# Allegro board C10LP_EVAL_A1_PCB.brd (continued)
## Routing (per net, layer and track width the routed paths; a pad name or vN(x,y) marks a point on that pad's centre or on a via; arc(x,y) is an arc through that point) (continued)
RG_RXD1: length 2
  TOP w0.142: R105.2 26.64,46.35 26.61,46.39 U14.4
RG_RXD2: length 2.1
  TOP w0.142: U14.3 26.11,46.01 25.63,45.53 R106.2
RG_RXD3: length 2.2
  TOP w0.142: U14.1 25.11,46.49 24.99,46.38 24.99,45.63 R107.2
RUP2: length 5.4
  TOP w0.135: U1.M10 41.48,27.32 v2(41.48,27.3)
  BOTTOM w0.135: R12.2 46.2,27.68 41.85,27.68 v2(41.48,27.3)
SYS_CONF_DONE: length 39.5
  TOP w0.135: U3.K1 52.51,67.47 54.18,65.81 56.08,65.81 57.18,64.72 57.18,64.16 58.98,62.36 62.64,62.36 63.88,61.11 66.22,61.11 67.77,59.56 69.85,59.56 71.93,57.48 71.93,50.14 72.95,49.12 77.42,49.12 78.11,48.44 D5.2
SYS_CONF_DONE_R: length 1.2
  TOP w0.135: D5.1 R135.2
SYS_I2C_SCL: length 98.6
  TOP w0.135: U3.G13 41.12,65.07 41.05,65.15 40.2,65.15 R55.2 40.22,64.69 40.67,64.69 41.05,64.31 v1(41.05,63.37)
  ART03 w0.102: v1(72.47,67.03) 71.98,66.55 71.98,61.24 78.87,54.36 78.87,52.32 77.06,50.52 77.06,37.26 77.7,36.63 77.7,34.39 77.52,34.21 77.52,26.23 v1(78.05,25.69)
  BOTTOM w0.135: v1(78.05,25.69) R263.1 ; v1(41.05,63.37) 41.07,63.35 41.99,63.35 42.44,62.89 42.9,62.89 43.38,63.37 44.63,63.37 44.94,63.68 44.94,64.04 45.75,64.85 45.75,66.45 45.97,66.67 46.33,66.67 47.29,67.64 47.29,70.79 49.28,72.77 53.82,72.77 58.09,77.04 66.99,77.04 68.15,75.88 68.15,74.75 71.02,71.88 71.02,68.48 v1(72.47,67.03)
SYS_I2C_SDA: length 82.7
  TOP w0.135: U3.H8 v2(46.15,66.28)
  ART03 w0.102: v1(78.31,35.56) 78.31,36.73 77.5,37.54 77.5,50.29 79.32,52.12 79.32,54.51 72.49,61.34 v1(72.49,66.19)
  BOTTOM w0.135: R264.1 78.82,28.59 R56.2 79.21,29.5 79.4,29.69 79.4,30.96 78.66,31.7 78.66,34.7 78.31,35.05 v1(78.31,35.56) ; v1(72.49,66.19) 69.88,68.81 69.88,72.31 67.55,74.64 67.55,75.83 66.8,76.58 58.29,76.58 53.98,72.26 49.59,72.26 48.15,70.82 48.15,67.61 48.01,67.48 47.49,67.48 46.29,66.28 v2(46.15,66.28)
TPIAN: length 35.8
  TOP w0.107: U14.27 29.61,54.35 29.69,54.43 29.69,57.48 32.13,59.92 32.74,60.53 33.5,60.53 38.35,65.38 38.35,76.67 35.48,79.54 35.48,80.75 35.28,80.95 35.28,81.2 35.48,81.41 35.48,81.65 35.28,81.85 35.12,81.85 34.89,81.62 34.68,81.62 34.46,81.85 34.28,81.85 33.73,81.31 U28.11
TPIAP: length 36
  TOP w0.107: U28.12 33.73,82.58 34.12,82.18 35.42,82.18 35.81,81.79 35.81,79.68 38.68,76.81 38.68,65.24 33.64,60.2 32.88,60.2 30.02,57.34 30.02,54.38 30.11,54.3 U14.26
TPIBN: length 31.9
  TOP w0.107: U28.8 33.73,77.5 34.27,78.03 34.66,78.03 34.85,77.84 34.85,77.5 35.08,77.27 35.42,77.27 35.59,77.1 35.59,76.76 35.79,76.56 36.13,76.56 37.24,75.45 37.24,65.85 33.39,62 31.36,62 28.69,59.33 28.69,54.4 28.61,54.31 U14.29
TPIBP: length 32
  TOP w0.107: U28.9 33.73,78.77 34.13,78.36 34.79,78.36 35.08,78.07 37.57,75.59 37.57,65.71 33.53,61.67 31.5,61.67 29.02,59.2 29.02,54.47 29.11,54.38 U14.28
TPICN: length 29.2
  TOP w0.107: U28.5 33.73,73.69 34.2,74.16 34.48,74.16 34.75,73.89 34.98,73.89 35.24,74.16 35.57,74.16 36.12,73.61 36.12,73.25 35.86,73 35.86,72.8 36.12,72.54 36.12,66.48 33.06,63.42 30.09,63.42 27.19,60.53 27.19,56.31 R108.2 27.19,55.37 27.19,54.5 27.11,54.41 U14.32
TPICP: length 29.3
  TOP w0.107: U14.31 27.61,54.41 27.52,54.5 27.52,55.37 R110.2 27.52,56.31 27.52,60.39 30.23,63.09 33.2,63.09 36.45,66.34 36.45,73.75 35.71,74.49 34.2,74.49 33.73,74.96 U28.6
TPIDN: length 24.9
  TOP w0.107: U14.34 26.11,54.43 26.19,54.51 26.19,55 25.55,55.64 25.55,61.35 30.34,66.14 33.88,66.14 35.03,67.28 35.03,67.51 34.78,67.76 34.78,68.11 35.03,68.35 35.03,68.99 34.72,69.29 34.72,69.6 35,69.87 35,70.12 34.75,70.37 34.23,70.37 33.73,69.88 U28.2
TPIDP: length 25
  TOP w0.107: U14.33 26.61,54.42 26.52,54.51 26.52,55.14 25.88,55.78 25.88,61.21 30.48,65.81 34.02,65.81 35.36,67.15 35.36,70.23 34.89,70.7 34.18,70.7 33.73,71.15 U28.3
USB_5V: length 8.8
  BOTTOM w0.508: 71.32,63.35 71.22,63.35 70.71,63.86 65.84,63.86 64.95,64.74 64.95,65.41 64.36,65.99 R31.1
USB_ADDR0: length 26.3
  TOP w0.135: U1.A10 41.84,37.7 41.84,38.14 41.58,38.4 41.58,40.39 44.42,43.23 44.42,54.04 45.35,54.97 45.35,56.56 46.23,57.44 46.23,59.16 U3.A7
USB_ADDR1: length 25.9
  TOP w0.135: U1.A11 v2(42.64,37.32) ; v1(43.41,44.35) 42.8,44.96 42.8,49.33 43.13,49.66 43.13,56.26 43.94,57.07 43.94,58.75 44.95,59.75 U3.A10
  ART03 w0.102: v2(42.64,37.32) 42.24,37.72 42.24,43.64 42.95,44.35 v1(43.41,44.35)
USB_CLK: length 71.6
  TOP w0.135: v1(67.67,72.69) 67.49,72.69 67.49,72.69 U6.13
  ART03 w0.102: v1(67.67,72.69) 68.63,71.73 68.63,67.03 69.42,66.24 69.42,63.3 68.2,62.08 67.16,62.08 66.55,61.47 66.55,59.05 66.4,58.9 66.4,49.35 67.74,48.01 67.74,34.44 66.78,33.48 64.06,33.48 63.63,33.91 62.87,33.91 62.53,33.58 53.75,33.58 48.44,38.89 v1(46.86,38.89)
  BOTTOM w0.135: R248.1 42.63,38.89 v1(46.86,38.89) ; v1(67.67,72.69) 67.42,72.94 R247.2
USB_DATA0: length 25.8
  TOP w0.135: U1.A15 45.84,37.56 46.23,37.95 46.23,39.14 48.46,41.38 48.46,55.17 50.06,56.77 50.06,58.27 50.55,58.76 50.55,60.27 U3.A3
USB_DATA1: length 28.3
  TOP w0.135: U1.B14 45.44,36.08 45.44,37.79 45.77,38.13 45.77,39.45 47.32,41 47.32,44.17 48.07,44.93 48.07,48.62 47.32,49.38 47.32,52.4 48.07,53.15 48.07,55.33 49.67,56.93 49.67,58.46 50.16,58.95 50.16,60.69 U3.B3
USB_DATA2: length 26.4
  TOP w0.135: U1.A14 45.04,38.05 45.31,38.33 45.31,39.75 46.91,41.35 46.91,44.35 47.69,45.12 47.69,48.38 46.91,49.15 46.91,52.72 47.69,53.49 47.69,55.51 49.29,57.11 49.29,58.62 49.75,59.08 U3.A4
USB_DATA3: length 28.3
  TOP w0.135: U1.B13 44.64,36.08 44.64,39.97 46.51,41.83 46.51,44.55 47.3,45.34 47.3,48.11 46.51,48.89 46.51,52.98 47.3,53.77 47.3,55.68 48.34,56.72 48.34,58.48 49.38,59.52 49.38,60.71 U3.B4
USB_DATA4: length 26.6
  TOP w0.135: U3.A5 48.95,59.64 47.82,58.51 47.82,56.78 46.91,55.87 46.91,54.08 46.1,53.27 46.1,48.51 46.91,47.71 46.91,45.51 46.1,44.7 46.1,42.09 44.04,40.03 44.04,38.28 44.24,38.08 U1.A13
USB_DATA5: length 28.6
  TOP w0.135: U1.B12 43.84,36.08 43.84,37.9 43.51,38.23 43.51,40.18 45.69,42.37 45.69,44.86 46.52,45.68 46.52,47.38 45.69,48.21 45.69,53.58 46.52,54.41 46.52,56.05 47.43,56.95 47.43,58.67 48.54,59.78 48.54,60.67 U3.B5
USB_DATA6: length 26.2
  TOP w0.135: U3.A6 48.15,60.03 47.51,59.39 47.51,59.3 47.04,58.84 47.04,57.15 46.13,56.24 46.13,54.61 45.3,53.78 45.3,42.79 42.9,40.39 42.9,38.15 43.48,37.57 43.48,36.52 U1.A12
USB_DATA7: length 28
  TOP w0.135: U3.B6 47.75,60.67 47.75,60.09 46.62,58.96 46.62,57.28 45.74,56.4 45.74,54.79 44.86,53.9 44.86,43.03 42.24,40.41 42.24,36.08 U1.B10
USB_DISABLEN: length 21.7
  TOP w0.135: v1(39.52,69.9) 39.52,68.96 41.81,66.67 U3.J13 ; J2.2 v1(50.44,75.44)
  BOTTOM w0.135: v1(50.44,75.44) 50.43,75.43 R59.1 47.98,74.3 47.88,74.19 42.62,74.19 41.38,72.95 41.33,72.95 40.16,71.78 40.16,70.48 39.57,69.9 v1(39.52,69.9)
USB_EMPTY: length 35.3
  TOP w0.135: U3.E6 47.73,63.06 v2(47.73,62.23) ; v2(45.44,34.48) U1.D14
  ART03 w0.102: v2(47.73,62.23) 48.13,61.82 48.13,59.21 48.31,59.03 48.31,45.14 45.85,42.67 45.85,34.89 v2(45.44,34.48)
  BOTTOM w0.135: v2(47.73,62.23) 48.16,61.8 48.16,61.32 47.83,60.99 47.83,59.11 48.23,58.7 R52.1
USB_FULL: length 32.5
  TOP w0.135: v2(43.84,34.48) U1.D12 ; U3.C9 v2(45.35,61.47)
  ART03 w0.102: v2(45.35,61.47) 45.8,61.02 45.8,60.35 46.96,59.18 46.96,45.14 44.25,42.42 44.25,34.89 v2(43.84,34.48)
  BOTTOM w0.135: v2(45.35,61.47) 44.4,60.53 44.4,60.21 R51.1
USB_OEN: length 31
  TOP w0.135: U3.A9 45.31,59.84 45.31,57.67 44.58,56.94 44.58,55.47 43.54,54.43 43.54,45.24 v1(43.43,45.14) ; v2(41.44,32.88) U1.F9
  ART03 w0.102: v1(43.43,45.14) 42.75,45.14 41.83,44.22 41.83,36.83 41.05,36.04 41.05,34.29 41.25,34.09 41.58,34.09 41.83,33.83 41.83,33.27 v2(41.44,32.88)
USB_RDN: length 28.9
  TOP w0.135: U1.D11 v2(43.04,34.48) ; v1(43.41,43.54) 42.27,44.68 42.27,49.53 42.67,49.94 42.67,56.59 43.48,57.4 43.48,58.95 44.56,60.03 44.56,60.69 U3.B10
  ART03 w0.102: v1(43.41,43.54) 43.46,43.48 43.46,34.9 v2(43.04,34.48)
USB_RESETN: length 28
  TOP w0.135: U1.C9 40.64,35.28 40.64,40.08 43.97,43.41 43.97,54.15 44.97,55.15 44.97,56.78 45.8,57.61 45.8,59.53 U3.A8
USB_SCL: length 31.3
  TOP w0.135: v2(45.44,35.28) U1.C14 ; U3.E8 v2(46.15,63.07)
  ART03 w0.102: v2(46.15,63.07) 46.53,62.69 46.53,60.3 47.35,59.49 47.35,44.86 45.44,42.95 v2(45.44,35.28)
  BOTTOM w0.135: R54.1 45.4,62.33 v2(46.15,63.07)
USB_SDA: length 34
  TOP w0.135: U1.E9 v2(41.44,33.68) ; U3.C10 v2(44.55,61.47)
  ART03 w0.102: v2(44.55,61.47) 44.88,61.14 44.88,60.58 46.61,58.85 46.61,49.71 41.38,44.48 41.38,38.51 40.64,37.77 40.64,36.7 40.79,36.55 40.79,33.88 41,33.68 v2(41.44,33.68)
  BOTTOM w0.135: v2(44.55,61.47) 44.15,61.07 44.15,60.92 R53.1
USB_WRN: length 28
  TOP w0.135: U3.A11 43,59.13 43,58.09 42.72,57.81 41.88,57.81 40.26,56.18 40.26,51.66 41.81,50.11 41.81,44.04 v1(42.7,43.15) ; v2(43.05,36.91) 43.05,36.09 U1.B11
  ART03 w0.102: v1(42.7,43.15) 43.05,42.8 v2(43.05,36.91)
USER_DIP0: length 69.1
  TOP w0.135: v1(66.94,53.84) R147.1 68.21,53.84 68.4,54.03 SW1.6
  TOP w0.137: v2(47.5,27.68) U1.M16
  ART03 w0.102: v1(70.38,50.65) 73.89,50.65 75.06,49.48 75.06,30.71 74.12,29.77 74.12,28.3 74.35,28.07 74.35,26.9 73,25.55 68.12,25.55 67.34,24.77 66.8,24.77 64.95,22.91 63.88,22.91 57.73,29.06 47.37,29.06 47.02,28.7 47.02,28.09 47.43,27.68 v2(47.5,27.68)
  BOTTOM w0.135: v1(66.94,53.84) 70.13,50.65 v1(70.38,50.65)
USER_DIP1: length 59.7
  TOP w0.135: U1.A8 v2(40.24,37.04) ; SW1.7 68.2,52.76 68.11,52.67 R146.1 v1(66.94,52.67) ; v1(69.01,31.42) 68.12,30.53 63.75,30.53 63.32,30.96 61.57,30.96 59.94,32.59 53.39,32.59 50.95,35.03 v1(49.86,35.03)
  ART03 w0.102: v1(69.01,31.42) 69.88,32.28 69.88,47.6 68.55,48.92 68.55,51.05 v1(66.94,52.67) ; v1(46.86,37.8) 46.58,37.52 46.58,36.7 47.6,35.69 48.59,35.69 49.25,35.03 v1(49.86,35.03)
  BOTTOM w0.135: v1(46.86,37.8) 44.55,37.8 43.18,36.42 40.86,36.42 v2(40.24,37.04)
USER_DIP2: length 51
  TOP w0.135: v1(66.92,50.46) R145.1 67.64,50.93 68.2,51.49 SW1.8 ; U1.A9 v2(41.04,37.04)
  ART03 w0.102: v1(49.53,37.13) 53.49,33.17 62.71,33.17 63.02,33.48 63.47,33.48 63.91,33.05 67.06,33.05 68.15,34.14 68.15,49.23 v1(66.92,50.46)
  BOTTOM w0.135: v2(41.04,37.04) 41.74,37.04 43.08,38.38 48.29,38.38 v1(49.53,37.13)
USER_LED0: length 57.4
  TOP w0.135: U1.L14 v2(45.44,28.08) ; D6.2 78.32,43.23 78.16,43.07 78.16,41.48 77.7,41.02 74.78,41.02 74.24,41.55 v1(72.62,41.55)
  ART03 w0.102: v2(45.44,28.08) 45.78,28.08 47.19,29.49 57.94,29.49 64.03,23.39 64.85,23.39 66.62,25.17 67.08,25.17 67.87,25.96 72.34,25.96 73.33,26.95 73.33,29.79 74.42,30.89 74.42,39.75 v1(72.62,41.55)
USER_LED0_R: length 1.2
  TOP w0.135: D6.1 R138.2
USER_LED1: length 52
  TOP w0.135: 47.19,28.88 47.25,28.93 47.93,28.93 v1(48.31,28.55) ; v1(75.59,35.74) 76.23,36.37 77.65,36.37 78.11,36.83 78.11,37.74 78.38,38.02 D7.2
  TOP w0.137: U1.K15 46.24,28.88 47.19,28.88
  ART03 w0.102: v1(75.59,35.74) 75.59,27.53 73.13,25.07 68.28,25.07 67.54,24.33 66.95,24.33 65.53,22.91 65.53,21.26 64.92,20.65 63.4,20.65 62.97,21.08 62.97,23.19 57.58,28.58 51.49,28.58 51,28.09 49.12,28.09 48.77,28.45 48.41,28.45 v1(48.31,28.55)
USER_LED1_R: length 1.2
  TOP w0.135: D7.1 R140.2
USER_LED2: length 42.2
  TOP w0.135: v2(45.44,29.68) U1.J14 ; D8.2 78.24,32.82 77.3,31.88 74.85,31.88 73.28,30.3 v1(72.14,30.3)
  ART03 w0.102: v2(45.44,29.68) 45.66,29.9 58.19,29.9 61.79,26.3 63.08,26.3 63.97,25.41 65.27,25.41 66.34,26.49 72.29,26.49 72.85,27.05 72.85,27.46 72.14,28.17 v1(72.14,30.3)
USER_LED2_R: length 1.2
  TOP w0.135: R142.2 D8.1
USER_LED3: length 39.9
  TOP w0.135: v1(72.19,27.2) 72.26,27.13 74.57,27.13 75.06,27.61 D9.2 ; v2(44.64,29.68) U1.J13
  ART03 w0.102: v1(72.19,27.2) 70.89,28.5 69.7,28.5 68.86,27.66 65.89,27.66 65.53,27.3 65.53,26.34 65.15,25.96 64.01,25.96 63.42,26.54 63.42,27.18 60.3,30.3 45.26,30.3 v2(44.64,29.68)
USER_LED3_R: length 1.2
  TOP w0.135: D9.1 R143.2
USER_PB0: length 36.8
  TOP w0.135: S3.2 68.09,38.01 68.04,37.96 C206.1 R137.1 67.58,36.83 v1(66.83,36.83) ; 61.09,27.79 v1(62,26.87)
  TOP w0.137: U1.E15 46.24,33.68 47.88,33.68 49.58,31.98 51.36,31.98 52.58,30.76 58.12,30.76 61.09,27.79
  BOTTOM w0.135: v1(66.83,36.83) 65.28,36.83 61.11,32.66 61.11,27.74 61.98,26.87 v1(62,26.87)
USER_PB1: length 33.2
  TOP w0.135: v1(49.61,32.66) 51.33,32.66 52.78,31.22 58.52,31.22 v1(62,27.74) ; v1(63.25,33.02) 66.99,33.02 R139.1 C207.1 68.34,33.54 68.4,33.59 S4.2 ; v2(45.44,32.88) U1.F14
  ART03 w0.102: v1(49.61,32.66) 49.39,32.88 v2(45.44,32.88)
  BOTTOM w0.135: v1(63.25,33.02) 61.7,31.47 61.7,28.04 v1(62,27.74)
USER_PB2: length 34.2
  TOP w0.135: S5.2 68.4,29.18 68.39,29.17 C208.1 R141.1 66.64,27.9 66.17,28.37 v1(66.17,29.97) ; v2(43.04,35.28) U1.C11
  ART03 w0.102: v1(66.17,29.97) 65.15,30.99 63.73,30.99 61.95,32.77 53.31,32.77 49.89,36.2 48.62,36.2 v1(47.62,37.19)
  BOTTOM w0.135: v1(47.62,37.19) 47.62,37.19 47.52,37.29 45.05,37.29 v2(43.04,35.28)
USER_PB3: length 37.8
  TOP w0.135: v2(41.44,34.48) U1.D9 ; v1(63.17,25.53) 65.51,25.53 66.21,24.83 66.21,24.28 66.6,23.89 R144.1 C209.1 68.38,24.75 68.4,24.77 S6.2
  ART03 w0.102: v2(41.44,34.48) 41.57,34.48 41.99,34.06 49.25,34.06 50.95,32.36 61.67,32.36 v1(62.56,31.47)
  BOTTOM w0.135: v1(62.56,31.47) 62.26,31.17 62.26,29.21 63.17,28.3 v1(63.17,25.53)
VTAP_BYPASSN: length 56.7
  TOP w0.135: U3.K10 v2(44.55,67.07) ; v1(68.76,56.31) 68.53,56.31 67.98,55.77 R148.1 68.11,55.3 SW1.5
  ART03 w0.102: v1(68.76,56.31) 70.43,57.99 70.43,69.29 69.67,70.05 v1(69.67,74.98)
  BOTTOM w0.135: v1(69.67,74.98) 69.67,75.65 67.37,77.95 57.63,77.95 53.37,73.69 48.64,73.69 46.74,71.78 46.74,68.53 46.48,68.28 45.98,68.28 45.74,68.04 45.74,67.71 45.51,67.47 44.94,67.47 v2(44.55,67.07)
XA: length 3.9
  BOTTOM w0.135: U31.2 75.82,29.11 75.5,29.43 C66.2 75.5,30.31 74.97,30.85 Y3.3
XB: length 6.7
  BOTTOM w0.135: U31.3 76.32,29.1 76.64,29.43 C73.2 76.64,30.31 76.83,30.51 77.04,30.51 77.47,30.94 77.47,33.02 Y3.1
N16637352: length 3.1
  TOP w0.381: U13.A1 45.54,12.94 46.15,12.32 R92.2
N16666559: length 0.8
  TOP w0.508: R95.2 C47.1
N16670783: length 1.7
  TOP w0.135: v1(23.5,50.22) 23.6,50.32
  TOP w0.142: 23.6,50.32 U14.43
  BOTTOM w0.135: R100.2 23.58,50.3 v1(23.5,50.22)
N16798884: length 1.1
  BOTTOM w0.135: C15.2 36.21,84.1 R44.1
N16807169: length 2.6
  TOP w0.142: v1(23.19,49.58) 23.32,49.71 23.77,49.71 23.89,49.82 U14.44
  BOTTOM w0.135: R101.2 22.23,48.77 23.04,49.58 v1(23.19,49.58)
N16863501: length 1.9
  TOP w0.254: R65.1 60.85,36.34 61.35,36.85 U7.1
N16863513: length 1.9
  TOP w0.254: U7.8 57.47,36.85 58.03,36.29 R66.1
N16863764: length 1.9
  TOP w0.254: U8.1 53.18,39 52.75,39.43 R67.1
N16863768: length 2
  TOP w0.254: R68.1 52.52,42.23 53.18,42.89 U8.8
N16887336: length 2
  TOP w0.135: R11.1 28.75,36.7 28.37,37.08 U2.9
N16887348: length 2.1
  TOP w0.135: U2.1 v1(19.48,29.16)
  BOTTOM w0.135: v1(19.48,29.16) 19.47,29.17 R9.2
N16887422: length 2.7
  TOP w0.135: v1(27.99,29.31) 28.37,28.93 U2.8
  BOTTOM w0.135: v1(27.99,29.31) 28.37,29.69 R10.2
N16986323: length 3.4
  TOP w0.508: v1(20.9,80.04) U28.15
  BOTTOM w0.508: R208.1 v1(20.9,80.04)
N16986325: length 3.4
  TOP w0.508: v1(20.9,76.23) U28.18
  BOTTOM w0.508: R209.1 v1(20.9,76.23)
N16986327: length 3.4
  TOP w0.508: v1(20.9,72.42) U28.21
  BOTTOM w0.508: R210.1 v1(20.9,72.42)
N16986329: length 3.4
  TOP w0.508: v1(20.9,68.61) U28.24
  BOTTOM w0.508: v1(20.9,68.61) R211.1
N16993975: length 4.9
  TOP w0.135: R213.1 71.57,64.21 73.23,65.87 J17.4
N17040639: length 2.3
  TOP w0.254: U11.8 53.18,49.15 53.01,48.98 R79.1
N17040659: length 1.9
  TOP w0.254: R78.1 52.72,46.19 53.18,45.73 U11.1
N17050331: length 3.8
  BOTTOM w0.406: L5.2 49.95,54.91 C30.1 50.66,54.93 U12.1
N17106026: length 2
  TOP w0.135: v1(11.96,57.71) 12.12,57.86 D10.2
  BOTTOM w0.135: R240.2 v1(11.96,57.71)
N17106333: length 1.9
  TOP w0.135: v1(11.99,59.33) 12.04,59.39 D11.2
  BOTTOM w0.135: R241.2 12.09,59.23 v1(11.99,59.33)
N17106465: length 1.9
  TOP w0.135: v1(11.99,60.73) 12.14,60.88 D12.2
  BOTTOM w0.135: R242.2 v1(11.99,60.73)
N17132385: length 7.9
  TOP w0.135: R249.2 44.04,19.87 44.04,19.68 43.86,19.5 42.86,19.5 42.72,19.36 42.72,19.02 42.95,18.8 43.23,18.8 43.47,19.04 43.91,19.04 44.04,18.9 44.04,18.71 43.91,18.58 43.61,18.58 43.47,18.44 43.47,18.25 43.61,18.12 43.89,18.12 44.04,17.96 44.04,16.3 43.91,16.16 U13.D3
N17132392: length 6.6
  TOP w0.135: U13.D2 44.54,16.54 44.98,16.99 44.98,18.31 45.11,18.44 45.11,19.37 45.25,19.51 45.49,19.51 45.59,19.41 45.59,18.85 45.73,18.72 45.92,18.72 46.02,18.82 46.02,19.46 46.15,19.58 46.15,19.84 R250.2
N17132399: length 8
  TOP w0.135: R251.2 41.76,19.79 41.62,19.66 40.92,19.66 40.23,18.97 40.23,18.4 40.37,18.26 40.67,18.26 41.22,17.7 41.66,17.7 42.04,17.32 42.04,16.97 42.32,16.69 42.72,16.69 43.05,16.36 43.05,15.68 U13.C4
N17132406: length 6.4
  TOP w0.135: U13.D4 42.18,16.16 41.71,16.64 40.61,16.64 39.7,17.55 39.7,19.08 R252.2
N17132413: length 7.1
  TOP w0.135: R253.2 39.73,19.74 39.57,19.58 38.99,19.58 38.73,19.33 38.73,19.1 39.24,18.59 39.24,18.01 38.79,17.55 38.79,17.37 38.91,17.25 39.32,17.25 40.4,16.16 U13.D5
N17132420: length 6.9
  TOP w0.135: R254.2 42.4,20.12 42.27,19.98 42.27,19.35 42.11,19.2 41.17,19.2 40.94,18.98 40.94,18.71 41.17,18.49 41.48,18.49 41.73,18.75 42.34,18.75 43.25,17.84 43.25,17.65 43.1,17.49 43.1,17.3 43.24,17.16 U13.E3
N17132427: length 3.1
  TOP w0.135: U13.E2 44.54,19.8 R255.2
N17132434: length 6.6
  TOP w0.135: R256.2 46.89,19.71 46.99,19.61 47.35,19.61 47.45,19.51 47.45,19.18 47.31,19.04 47.12,19.04 46.96,19.2 46.58,19.2 46.48,19.1 46.48,18.9 46.58,18.8 46.71,18.8 46.84,18.66 46.84,18.47 46.69,18.31 46.46,18.31 46.33,18.18 46.33,17.96 46.18,17.8 46.01,17.8 45.9,17.92 45.9,18.13 45.76,18.27 45.57,18.27 45.44,18.13 45.44,17.26 U13.E1
N17132441: length 7.4
  TOP w0.135: R257.2 47.9,18.87 45.75,16.71 45.47,16.71 45.11,16.36 45.11,15.9 44.86,15.65 44.02,15.65 U13.C3
N17204392: length 1.8
  TOP w0.135: v1(45.09,14.61) 44.54,15.16 U13.C2
  BOTTOM w0.135: R258.1 45.66,14.05 v1(45.09,14.61)
N17217821: length 1.4
  TOP w0.135: U13.A2 44.51,13.16 v1(44.07,12.73)
  BOTTOM w0.135: R259.1 44.79,12.73 v1(44.07,12.73)
N17217865: length 1.8
  TOP w0.135: v1(40.98,13.72) 41.53,13.16 U13.A5
  BOTTOM w0.135: R260.1 40.92,13.65 v1(40.98,13.72)
N17225816: length 1
  TOP w0.305: R201.1 R192.1
N17244926: length 2.3
  TOP w0.508: U28.10 v1(31.65,80.04)
  BOTTOM w0.508: C160.1 v1(31.65,80.04)
N17244940: length 2.4
  TOP w0.508: U28.7 v1(31.6,76.23)
  BOTTOM w0.508: C161.1 v1(31.6,76.23)
N17244954: length 2.2
  TOP w0.508: U28.4 v1(31.67,72.42)
  BOTTOM w0.508: C162.1 v1(31.67,72.42)
N17244968: length 2.1
  TOP w0.508: U28.1 v1(31.75,68.61)
  BOTTOM w0.508: C163.1 v1(31.75,68.61)
N17285342: length 5
  BOTTOM w0.305: U31.1 75.32,26.52 74.89,26.1 C67.2 73.01,26.1 73,26.11 L10.2
N17285440: length 2.7
  BOTTOM w0.135: R264.2 78.35,27.62 77.77,27.05 77.42,27.05 77.32,27.15 U31.5
N17285442: length 3.6
  BOTTOM w0.135: R263.2 78.14,26.58 77.95,26.39 77.19,26.39 76.82,26.76 U31.4
N17285490: length 2.6
  BOTTOM w0.135: U31.10 75.32,23.22 75.01,22.91 74.02,22.91 73.85,23.08 R152.1
N17285492: length 3
  BOTTOM w0.135: U31.9 75.82,24.62 75.67,24.77 75.01,24.77 74.78,24.54 R155.1
N17285494: length 2.3
  BOTTOM w0.135: U31.6 77.32,23.22 77.45,23.09 77.7,23.09 78.11,23.49 78.47,23.49 R157.1
N17285521: length 1.6
  BOTTOM w0.254: C72.2 76.95,22.69 76.82,22.83 U31.7
N17451710: length 1.2
  TOP w0.135: C17.2 R57.1
N17512425: length 4
  BOTTOM w0.406: U12.2 53.58,55.87 53.28,56.17 C31.1 R295.1
N17554452: length 38.9
  ART03 w0.305: v1(78.11,52.53) 76.05,54.58 76.05,55.02 71.07,59.99 71.07,74.45 v1(70.59,74.93)
  BOTTOM w0.305: R300.2 70.28,84.3 70.59,84 v1(70.59,74.93) ; C210.1 76.19,53.37 R298.1 76.25,53.38 R299.2 77.32,53.31 v1(78.11,52.53)
N17555511: length 1.8
  BOTTOM w0.305: R299.1 77.32,56.01 Q30.G
N17689344: length 5.6
  TOP w0.135: D4.2 79.12,55.05 R309.2 78.65,55.08 78.49,55.24 78.49,56.72 79.05,57.28 Q5.3

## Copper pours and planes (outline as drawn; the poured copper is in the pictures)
5V_DCIN on TOP (solid shape): 75.34,82.4 75.34,78 74.8,77.47 72.59,77.47 72.11,77.95 72.11,81.31 71.45,81.97 68.3,81.97 67.92,81.58 67.87,81.58 67.87,81.53 67.79,81.46 65.28,81.46 65.1,81.64 65.1,84.1 65.51,84.51 73.23,84.51
5V_DCIN on BOTTOM (solid shape): 68.96,84.53 68.96,83.52 69.55,82.93 69.55,81.69 69.53,81.65 69.49,81.64 68.1,81.64 67.94,81.48 65.28,81.48 65.13,81.64 65.13,84.35 65.43,84.66 68.83,84.66
GND on TOP (solid shape): 15.01,66.8 15.01,63.04 14.73,62.76 9.86,62.76 9.63,62.99 9.63,66.75 10.06,67.18 14.63,67.18
GND on TOP (solid shape): 25.83,20.09 25.83,19.43 25.19,18.79 21.21,18.79 20.85,19.15 20.85,20.14 20.99,20.28 25.65,20.28
GND on TOP (solid shape): 37.92,45.9 37.92,44.88 37.69,44.65 35.28,44.65 35.08,44.86 35.08,45.9 35.28,46.1 37.72,46.1
GND on TOP (solid shape): 65.89,72.62 65.89,67.46 65.46,67.03 60.43,67.03 60.05,67.41 60.05,72.69 60.2,72.85 65.66,72.85
GND on TOP (solid shape): 20.55,16.31 21.31,16.31 21.59,16.03 21.59,14.73 20.6,13.74 18.77,13.74 18.44,14.07 18.44,16.87 18.62,17.04 19.81,17.04
GND on TOP (solid shape): 67.79,58.93 68.71,58.93 69.06,58.57 69.06,58.01 68.63,57.58 67.08,57.58 64.82,59.84 64.82,60.25 65.02,60.45 66.27,60.45
GND on TOP (solid shape): 38.99,14.3 38.99,9.86 36.02,9.86 36.02,11.02 35.81,11.23 34.67,11.23 34.49,11.05 34.49,10.29 33.93,10.29 33.93,11.13 33.78,11.28 33.78,14.99 38.3,14.99
GND on TOP (solid shape): 55.24,24.84 55.14,24.74 55.14,19.28 55.12,19.26 54.36,19.26 54.23,19.38 54.23,20.09 54.03,20.29 54.03,20.29 53.9,20.42 52.37,20.42 52.21,20.59 52.21,21.95 52.83,22.57 52.83,25.12 53.66,25.95 55.24,25.95
GND on TOP (solid shape): 77.55,56.95 78.11,56.39 78.11,55.27 77.98,55.14 77.83,55.14 77.77,55.19 77.75,55.19 77.72,55.22 77.72,55.78 77.57,55.93 76.2,55.93 75.97,55.7 75.97,51.51 75.77,51.31 75.39,51.31 74.98,51.71 74.98,57.68 75.31,58.01 77.55,58.01
GND on TOP (solid shape): 54.74,17.86 57.03,17.86 57.25,18.08 59.97,18.08 60.35,18.47 61.18,18.47 61.35,18.29 61.35,14.77 60.49,13.91 59.35,13.91 57.68,12.24 56.77,12.24 56.41,12.6 56.41,14.58 56.64,14.81 57.38,14.81 57.49,14.92 57.49,16.09 57.54,16.14 58.48,16.14 58.55,16.21 58.55,16.84 58.27,17.12 56.97,17.12 56.95,17.1 52.46,17.1 52.46,18.75 54.74,18.75
GND on TOP (solid shape): 50.68,17.47 50.9,17.47 50.94,17.46 50.95,17.42 50.95,17.17 51.13,17 51.13,16.96 51.12,16.94 51.04,16.82 51.01,16.68 51,16.66 50.37,16.03 49.35,16.03 49.32,16.04 49.3,16.08 49.3,16.56 49.45,16.71 50.01,16.71 50.04,16.74 50.15,16.74 50.15,16.85 50.24,16.94 50.24,17.5 50.26,17.54 50.29,17.55 50.6,17.55
GND on TOP (solid shape): 21.69,48.21 21.73,48.19 21.74,48.16 21.74,47.68 21.7,47.63 21.67,47.62 21.64,47.62 21.2,47.53 21.11,47.09 21.12,47.06 21.1,47.03 21.03,46.96 21.03,46.38 20.66,46.01 20.52,46.01 20.22,45.71 19.63,45.71 19.63,45.69 18.77,45.69 18.61,45.85 18.61,47.64 18.92,47.96 20.8,47.96 21.06,48.21
GND on BOTTOM (solid shape): 38.23,12.52 38.23,11.51 38,11.28 35.61,11.28 35.31,11.58 33.91,11.58 33.91,12.75 38,12.75
GND on BOTTOM (solid shape): 46.48,47.32 46.48,43.99 45.49,43.99 45.49,47.32 45.72,47.55 46.25,47.55
GND on BOTTOM (solid shape): 53.64,21.84 53.64,20.73 53.49,20.57 52.4,20.57 52.25,20.73 52.25,21.84 52.35,21.95 53.54,21.95
GND on BOTTOM (solid shape): 12.29,66.22 12.29,63.17 11.71,62.59 7.49,62.59 7.49,66.8 11.71,66.8
GND on BOTTOM (solid shape): 76.3,21.92 76.05,21.67 76.05,21.21 75.82,20.98 74.55,20.98 74.27,21.26 74.27,22.07 74.65,22.45 76.3,22.45
GND on BOTTOM (solid shape): 55.22,18.44 61.29,18.44 61.67,18.06 61.67,15.27 61.14,14.73 55.19,14.73 52.35,17.58 52.35,18.59 53.01,19.25 54.41,19.25
GND on BOTTOM (solid shape): 29.41,19.02 29.41,18.72 29.26,18.57 28.75,18.57 28.47,18.29 27.41,18.29 27.41,18.87 27.51,18.97 28.75,18.97 28.93,19.15 29.29,19.15
GND on BOTTOM (solid shape): 71.32,54.61 71.32,53.11 71.3,53.09 71.3,51.31 71.22,51.23 70.27,51.23 70.21,51.18 70.12,51.18 68.99,52.32 68.99,54.2 69.57,54.79 71.15,54.79
GND on BOTTOM (solid shape): 79.38,75.82 79.41,75.8 79.43,75.77 79.43,74.37 78.97,73.91 72.11,73.91 71.93,74.09 71.93,75.49 72.26,75.82
GND on BOTTOM (solid shape): 60.15,61.86 60.74,61.86 60.79,61.81 61.16,61.81 61.37,61.6 61.37,60.76 61.2,60.59 61,60.59 60.99,60.58 59.21,60.58 58.93,60.86 58.93,61.85 58.95,61.87 60.15,61.87
GND on BOTTOM (solid shape): 25.42,18.66 19.58,18.66 19.33,18.4 19.33,17.77 20.72,16.37 20.72,14.37 19.96,13.61 18.69,13.61 18.24,14.07 18.24,19.47 18.41,19.64 20.63,19.64 20.85,19.42 23.14,19.42 23.14,20.31 25.42,20.31
GND on BOTTOM (solid shape): 26.04,27.18 26.04,23.42 25.76,23.14 24.66,23.14 23.64,22.12 23.64,20.94 23.52,20.82 22.75,20.82 22.74,20.83 22.74,22.51 22.82,22.59 22.82,26.61 22.75,26.68 22.75,27.37 25.84,27.37
GND on BOTTOM (solid shape): 64.64,73.27 65.47,73.27 66.29,72.44 66.29,72.38 66.32,72.35 66.32,72.11 66.27,72.06 66.27,66.73 65.99,66.45 65.1,66.45 64.92,66.62 60.48,66.62 60.44,66.64 60.43,66.67 60.43,69.19 59.77,69.85 59.77,71.98 59.74,72.01 59.74,72.92 60.1,73.28 64.64,73.28
GND on BOTTOM (solid shape): 53.68,25.43 53.82,25.43 53.87,25.38 53.95,25.38 53.98,25.36 54,25.33 54,25.32 54.26,25.32 54.26,25.33 54.27,25.36 54.31,25.38 54.43,25.38 54.58,25.22 54.58,24.1 53.9,23.42 53.11,23.42 52.98,23.55 52.98,25.37 53.06,25.45 53.65,25.45
GND on BOTTOM (solid shape): 27.51,53.64 28.83,53.64 28.98,53.8 28.98,54.05 29.21,54.28 30.12,54.28 30.43,53.98 30.43,52.6 30.45,52.58 30.45,50.6 30.86,50.19 30.86,48.77 29.97,47.88 29.97,47.09 29.74,46.86 28.93,46.86 28.57,47.22 28.57,47.57 28.42,47.73 25.45,47.73 24.84,48.34 24.84,49.35 25.45,49.96 25.45,52.07 24.82,52.7 24.82,53.82 25.35,54.36 26.8,54.36
GND on BOTTOM (solid shape): 41.25,19.94 41.29,19.92 41.3,19.89 41.3,18.65 41.15,18.5 41.15,17.85 41.22,17.77 41.22,17.75 41.58,17.4 41.6,17.4 41.72,17.27 41.88,17.27 41.92,17.26 41.94,17.22 41.94,16.9 41.93,16.89 41.68,16.89 41.61,16.81 41.57,16.81 41.52,16.76 39.7,16.76 39.17,17.3 38.33,17.3 38.07,17.55 38.07,18.95 38.79,19.66 40.56,19.66 40.84,19.94
GND on BOTTOM (solid shape): 73,46.96 73,46.8 72.99,46.79 72.97,46.79 72.97,46.78 72.85,46.65 72.85,46.41 72.82,46.38 72.82,44.81 72.75,44.73 71.89,44.73 71.76,44.6 71.73,44.6 71.27,44.15 71.27,43.51 71.26,43.47 71.22,43.46 70.61,43.46 70.43,43.28 70.43,41.22 70.99,40.67 70.99,36.4 70.98,36.36 70.94,36.35 70.1,36.35 69.55,35.79 68.55,35.79 68.4,35.94 68.4,44.32 68.58,44.5 70.59,44.5 71.17,45.09 71.17,46.25 71.19,46.29 71.22,46.3 72.29,46.3 72.44,46.46 72.44,46.87 72.61,47.04 72.92,47.04
GND on BOTTOM (solid shape): 46.94,15.39 46.94,14.5 46.69,14.25 46.27,14.25 46.23,14.26 46.22,14.3 46.22,14.43 45.8,14.43 45.47,14.76 45.47,14.77 45.07,15.02 44.7,14.73 44.63,14.67 44.54,14.69 44.47,14.76 44.47,14.77 43.91,14.97 43.74,14.4 43.74,14.3 43.66,14.25 43.61,14.25 43.41,14.45 43.41,15.52 43.42,15.56 43.46,15.57 46.76,15.57
GND on BOTTOM (solid shape): 37.47,63.4 37.83,63.4 37.93,63.37 38.03,63.38 38.12,63.34 38.14,63.25 38.28,62.83 38.71,62.78 38.81,62.78 38.86,62.69 38.86,62.15 38.15,62.15 38.1,62.1 38.01,62.1 37.93,62.14 37.91,62.22 37.7,62.67 37.21,62.58 37.13,62.54 37.06,62.58 36.57,62.67 36.36,62.22 36.33,62.14 36.26,62.1 36.04,62.1 35.79,61.85 31.85,61.85 31.72,61.98 30.25,61.98 30.25,62.56 31.04,62.56 31.19,62.71 31.19,63.35 30.78,63.75 29.97,63.75 29.76,63.97 29.76,66.95 33.91,66.95
GND on GND02 (solid shape): outline of 30918 points within 1.02,6.1 80.26,85.34
GND on GND05 (solid shape): outline of 34362 points within 1.02,6.1 80.26,85.34
GND on BOTTOM: 20.42,47.7 18.97,47.7 18.77,47.5 18.77,46.13 18.92,45.97 20.24,45.97 20.45,46.18 20.45,47.68
GND on BOTTOM: 20.09,53.11 20.09,51.46 20.35,51.21 20.17,51.03 18.57,51.03 18.19,51.41 18.19,52.96 18.36,53.14 20.07,53.14
GND_EARTH_ETH on BOTTOM (solid shape): 3.2,84.96 3.2,80.14 3.66,79.68 3.66,74.85 3.17,74.37 3.17,69.37 5.56,66.98 5.56,62.56 2.18,62.56 1.04,63.7 1.04,84.99 1.4,85.34 2.82,85.34
GND_EARTH_USB on BOTTOM (solid shape): 80.26,71.76 80.26,60.99 79.91,60.63 73.94,60.63 73.46,61.11 73.46,61.52 74.17,62.23 77.22,62.23 78.23,63.25 78.23,67.31 77.6,67.95 74.02,67.95 73.53,68.43 73.53,71.75 73.91,72.14 79.88,72.14
VCC_1.2V on TOP (solid shape): 58.09,24.59 59.84,24.59 59.99,24.43 59.99,22.99 59.18,22.17 59.18,19.12 58.55,18.49 57.41,18.49 57.41,19 57.15,19.26 55.76,19.26 55.63,19.38 55.63,20.78 55.76,20.91 55.76,25.96 56.72,25.96
VCC_1.2V on BOTTOM (solid shape): 60.83,25.81 60.83,24.26 59.79,23.22 56.97,23.22 56.72,22.96 55.19,22.96 55.07,23.09 55.07,24.51 55.27,24.71 57.96,24.71 58.29,25.04 58.29,26.03 60.6,26.03
VCC_1.8V on TOP (solid shape): 32.87,15.47 33.12,15.21 33.12,11.73 33.07,11.68 31.5,11.68 31.32,11.51 31.32,10.01 31.57,9.75 32.92,9.75 32.92,9.22 30.53,9.22 30.1,9.65 30.1,15.24 31.95,17.09 32.87,17.09
VCC_1.8V on BOTTOM (solid shape): 44.12,20.73 44.12,18.82 44.97,17.97 46.55,17.97 47.47,17.04 47.47,15.52 47.14,15.85 47.14,15.88 47.04,15.98 43.18,15.98 42.9,15.7 42.9,13.41 42.75,13.26 41.86,13.26 41.68,13.44 41.68,16.21 41.78,16.31 42.06,16.31 42.44,16.69 42.44,17.5 42.16,17.78 41.94,17.78 41.66,18.06 41.66,18.29 41.81,18.44 41.81,20.19 41.55,20.45 38.05,20.45 38.05,19.91 37.54,19.41 37.54,17.75 33.3,13.51 33.3,11.94 33.25,11.89 30.66,11.89 30.18,12.37 30.18,14.78 30.38,14.99 32.49,14.99 35.97,18.47 35.97,21.08 36.55,21.67 43.18,21.67
VCC_2.5V on BOTTOM (solid shape): 44.17,64.82 44.17,64.54 43.88,64.25 41.19,64.25 40.61,63.68 40.61,62.59 41.66,61.54 41.66,57.33 42.04,56.95 42.05,56.95 42.13,56.87 42.8,56.87 43.46,56.21 43.46,56.02 43.73,55.75 43.92,55.75 44.96,54.71 44.96,42.67 46.11,41.52 46.13,41.52 46.22,41.43 48.79,41.43 49.73,42.37 51.77,42.37 51.77,41.12 51.74,41.1 50.32,41.1 50.29,41.12 50.16,41.12 49.8,40.75 45.63,40.75 43.83,42.55 43.83,45.05 43.84,45.14 43.83,45.22 43.83,54.3 42.63,55.5 42.42,55.78 42.14,55.99 41.88,56.08 41.6,56.11 40.23,56.11 39.12,57.23 39.12,59.44 38.73,59.82 32.94,59.82 32.08,58.95 30,58.95 29.18,59.77 29.18,60.99 29.77,60.99 29.77,60.29 30.24,59.82 31.71,59.82 32.16,60.27 32.16,61.19 35.76,61.19 36.14,60.81 37.92,60.81 38.35,61.24 38.35,61.72 39.19,61.72 39.37,61.9 39.37,63.32 41.05,65 43.99,65
VCC_3.3V on TOP (solid shape): 22.12,24.69 22.12,23.9 21.84,23.62 18.8,23.62 18.47,23.95 18.47,25.88 18.59,26.01 20.8,26.01
VCC_3.3V on TOP (solid shape): 14.76,48.69 14.76,45.77 14.53,45.54 6.53,45.54 6.02,46.05 6.02,47.45 6.25,47.68 7.65,47.68 8.84,48.87 14.58,48.87
VCC_3.3V on BOTTOM (solid shape): 71.09,28.09 71.09,25.6 70.1,25.6 70.1,28.09 70.31,28.3 70.89,28.3
VCC_3.3V on BOTTOM (solid shape): 19.46,55.7 19.46,53.8 19.35,53.7 17.83,53.7 17.63,53.9 17.63,55.4 17.96,55.73 19.43,55.73
VCC_3.3V on BOTTOM (solid shape): 79.3,22.73 79.3,21.77 78.99,21.46 78.99,20.4 77.98,20.4 77.98,21.54 77.83,21.69 77.83,22.66 78.11,22.94 79.1,22.94
VCC_3.3V on BOTTOM (solid shape): 22.36,26.67 22.19,26.49 22.19,21.55 22.26,21.48 22.26,20.89 22.17,20.8 20.71,20.8 20.47,20.57 20.47,20.05 19.68,20.05 18.31,21.43 18.31,26.96 18.72,27.37 22.36,27.37
VCC_3.3V on ART03 (solid shape): outline of 1279 points within 62.15,6.25 80.01,24.18
VCC_3.3V on VCC04 (solid shape): outline of 16003 points within 13.92,22.61 79.63,84.33
VCC_3.3V on BOTTOM: 47.07,47.85 48.54,47.85 48.54,51.26 48.31,51.49 47.29,51.49 47.07,51.26
VCC_5V on TOP (solid shape): 27.89,65.2 27.89,64.87 26.62,63.6 25.48,63.6 25.27,63.8 25.27,65.35 25.45,65.53 27.56,65.53
VCC_5V on TOP (solid shape): 33.71,8.08 33.4,7.77 32.46,7.77 32.31,7.62 32.31,6.86 31.8,6.86 31.8,8.31 32.23,8.74 33.71,8.74
VCC_5V on TOP (solid shape): 53.87,19.38 53.75,19.26 51.66,19.26 51.44,19.48 51.44,19.77 51.57,19.91 53.87,19.91
VCC_5V on TOP (solid shape): 42.16,8.92 42.16,7.37 41.96,7.16 35.64,7.16 35.05,7.75 34.82,7.75 34.7,7.87 34.7,8.71 34.72,8.74 35.31,8.74 35.66,9.09 41.99,9.09
VCC_5V on TOP (solid shape): 54.54,15.9 54.54,15.08 54.81,14.81 54.99,14.81 55,14.81 55.75,14.81 55.91,14.66 55.91,12.24 55.68,12.01 53.64,12.01 53.44,12.22 53.44,13.13 53.44,14.78 53.6,14.94 53.6,15.83 53.73,15.95 54.49,15.95
VCC_5V on BOTTOM (solid shape): 38.56,59.39 38.56,57.33 38.38,57.15 37.41,57.15 37.21,57.35 37.21,57.84 37.31,57.94 37.31,59.41 38.53,59.41
VCC_5V on BOTTOM (solid shape): 13.21,24.38 13.21,21.84 12.95,21.59 11.94,21.59 11.66,21.87 11.66,24.64 12.95,24.64
VCC_5V on BOTTOM (solid shape): 27.13,21.13 27.13,20.65 27,20.52 26.75,20.52 26.45,20.82 26.38,20.82 26.38,20.82 24.15,20.82 24.02,20.94 24.02,21.74 24.28,22 26.26,22
VCC_5V on BOTTOM (solid shape): 28.96,63.8 28.7,63.55 28.7,62.79 28.14,62.79 28.12,62.81 25.3,62.81 25.2,62.92 25.2,65.89 26.26,66.95 28.96,66.95
VCC_5V on BOTTOM (solid shape): 24.28,17.39 24.28,16.12 24.28,16.12 24.28,13.84 24.27,13.83 24.27,13.53 23.75,13 21.64,13 21.48,13.16 21.48,16.12 21.74,16.37 23.08,16.37 23.39,16.69 23.43,17.52 24.15,17.52
VCC_5V on BOTTOM (solid shape): 75.9,39.19 76.01,39.19 76.03,39.17 77.29,39.17 77.55,38.91 79.04,38.91 79.08,38.9 79.1,38.86 79.1,37.08 78.33,36.32 75.18,36.32 73.23,34.37 73.23,31.42 72.57,30.76 69.93,30.76 69.89,30.77 69.88,30.81 69.88,35.2 70.48,35.81 71.48,35.81 71.65,35.99 71.65,40.03 71.68,40.06 75.03,40.06
VCC_5V on VCC04 (solid shape): outline of 11938 points within 2.03,7.11 79.63,66.65
VCC_5V_AR1 on BOTTOM (solid shape): outline of 87 points within 63.73,26.03 71.4,30.1
VCC_5V_AR2 on BOTTOM (solid shape): 36.65,56.59 37.41,55.83 37.41,54.64 36.91,54.13 35.79,54.13 35.41,54.51 35.41,59.41 36.65,59.41
VCC_5V_GPIO on BOTTOM (solid shape): 10.92,24.64 10.92,22.99 10.67,22.73 6.48,22.73 5.97,23.24 5.97,24.38 6.48,24.89 10.67,24.89
VCC_5V_IN on TOP (solid shape): 68.33,80.37 70.21,80.37 70.24,80.35 70.26,80.31 70.26,78.05 70.24,78.02 70.21,78 65.38,78 65.05,78.33 65.05,80.59 65.38,80.92 67.77,80.92
VCC_5V_IN on BOTTOM (solid shape): 69.55,81 69.58,80.99 69.6,80.95 69.6,78.74 69.04,78.18 67.67,78.18 67.52,78.32 65.41,78.32 65.41,78.33 65.41,80.11 66.29,81
VCC_5V_IN on BOTTOM (solid shape): outline of 230 points within 69.27,39.57 79.65,57.99
VCC_5V_IN on VCC04 (solid shape): outline of 2030 points within 64.66,52.25 79.6,84.51
A_GND on BOTTOM (solid shape): 57.18,63.68 57.18,62.15 57.45,61.87 58.32,61.87 58.35,61.86 58.37,61.82 58.37,59.84 58.06,59.54 56.18,59.54 56.03,59.69 56.03,63.75 56.24,63.96 56.9,63.96
A_GND on GND02 (solid shape): outline of 1321 points within 49.58,35.1 65.41,64.72
C10_VCCA_FLT on BOTTOM (solid shape): outline of 432 points within 42.42,32.59 49.78,36.65
C10_VCCA_FLT on ART03 (solid shape): outline of 1643 points within 37.24,26.67 43.71,33.71
C10_VCCD_PLL on TOP (solid shape): 56.13,27.81 56.13,27.05 55.96,26.87 53.34,26.87 53.09,26.87 51.66,25.45 51.66,23.98 51.67,23.97 51.67,23.93 50.32,22.58 49.87,22.58 49.2,21.91 48.98,21.91 48.97,21.91 48.52,21.91 48.34,22.09 48.34,22.45 50.14,24.26 50.17,24.27 50.21,24.27 50.72,24.34 50.75,24.85 50.75,25.86 52.97,28.07 55.87,28.07
C10_VCCD_PLL on BOTTOM (solid shape): 55.93,28.45 55.93,26.26 55.5,25.83 53.85,25.83 53.06,26.62 53.06,28.42 53.34,28.7 55.68,28.7
C10_VCCD_PLL on VCC04 (solid shape): outline of 1358 points within 36.2,26.04 54.61,34.92
C10_VCCINT on BOTTOM (solid shape): 57.18,21.77 59.31,21.77 59.39,21.84 61.49,21.84 61.57,21.77 61.57,19.13 61.44,19 55.58,19 55.35,19.23 55.35,20.85 55.12,21.08 55.12,22.35 55.17,22.4 56.54,22.4
C10_VCCINT on VCC04 (solid shape): outline of 4758 points within 37.64,16.71 62.51,33.5
C10_VCCIO_1.8V on BOTTOM (solid shape): 43.51,24.31 44.35,24.31 44.4,24.36 44.4,25.02 44.58,25.2 44.81,25.2 44.98,25.02 44.98,24.66 45.29,24.36 47.17,24.36 47.35,24.18 47.35,23.34 46.69,22.68 46.05,22.68 45.93,22.56 45.36,22.89 44.82,22.5 44.65,22.33 36.58,22.33 36.58,23.65 36.75,23.83 39.52,23.83 40.37,22.98 40.5,22.98 40.68,22.96 40.86,23 42.36,23 42.82,23.47 42.82,24.33 42.55,24.61 42.11,24.61 41.94,24.79 41.94,25.04 42.11,25.22 42.6,25.22
C10_VCCIO_3.3V on BOTTOM (solid shape): 48.54,47.19 48.54,45.39 48.26,45.11 48.26,41.99 48.18,41.91 47.37,41.91 47.27,42.01 47.27,45.11 47.07,45.31 47.07,47.22 48.51,47.22
C10_VCCIO_3.3V on ART03 (solid shape): outline of 533 points within 43.28,27.05 45.9,33.71
C10_VCCIO_3.3V on VCC04 (solid shape): outline of 1936 points within 29.72,23.24 48.63,43.92
ENET_REGO on TOP (solid shape): 21.72,53.67 22.15,53.67 23.44,52.37 23.44,52.27 23.37,52.2 22.58,52.2 22.46,52.31 22.4,52.31 22.39,52.3 19.61,52.3 19.13,52.78 19.13,54.15 19.61,54.64 19.61,54.86 19.71,54.97 20.42,54.97
ENET_VDD_1V on TOP (solid shape): 23.24,51.84 23.24,51.64 21.74,50.14 21.74,48.64 21.72,48.62 18.95,48.62 18.62,48.95 18.62,51.03 19.38,51.79 22.4,51.79 22.53,51.92 23.16,51.92
ENET_VDD_1V on BOTTOM (solid shape): 23.27,51.69 23.27,50.83 22.07,49.63 22.07,49.31 22.06,49.28 22.02,49.26 21.67,49.26 21.67,48.84 21.23,48.41 19.2,48.41 19,48.62 19,49.96 19.57,50.53 21.7,50.53 21.79,50.62 21.83,50.62 21.83,50.66 21.84,50.67 21.84,51.43 22.07,51.66 22.17,51.66 22.17,51.77 22.35,51.94 23.01,51.94
ENET_VDD_1V on BOTTOM (solid shape): 32.51,50.04 32.51,47.45 32.12,47.06 32.1,47.04 32.08,47.04 31.79,46.92 31.67,46.63 31.67,46.61 31.66,46.59 31.6,46.53 31.11,46.53 30.62,46.04 30.55,45.98 30.49,45.91 29.59,45.01 28.5,45.01 28.47,45.03 27.86,45.03 27.83,45.05 27.81,45.09 27.81,45.59 27.94,45.72 28.09,45.71 28.2,45.72 28.32,45.72 28.83,46.23 29.72,46.23 29.9,46.41 30.18,46.41 30.18,46.69 30.63,47.14 30.63,47.93 31.06,48.36 31.11,48.36 31.11,48.45 31.27,48.6 31.27,50.11 31.28,50.15 31.32,50.16 32.38,50.16
ENET_VDD_1V on VCC04 (solid shape): outline of 1184 points within 20.19,45.47 32.74,52.1
ENET_VDD_3.3V on BOTTOM (solid shape): outline of 171 points within 19.99,50.86 31.83,55.96
ENET_VDD_3.3V on ART03 (solid shape): outline of 1082 points within 20.47,43.05 28.65,55.55
M10_VCCA_3.3V on BOTTOM (solid shape): 65.07,57.96 66.83,57.96 66.98,58.12 68.38,58.12 68.4,58.09 68.4,57.1 68.25,56.95 63.73,56.95 63.25,57.43 63.25,58.75 63.35,58.85 64.19,58.85
M10_VCCA_3.3V on ART03 (solid shape): outline of 955 points within 43.89,48.49 64.36,68.12
USB_5V on BOTTOM (solid shape): 74.32,63.7 74.32,63.04 74.12,62.84 72.9,62.84 72.47,62.41 72.47,59.86 72.52,59.48 72.86,59.31 76.53,59.31 76.83,59 76.83,57.66 76.82,57.62 76.78,57.61 71.88,57.61 70.51,58.98 69.34,58.98 69.29,59.03 69.29,63.27 68.73,63.83 68.73,63.86 68.88,64.01 74.02,64.01
N16986355 on BOTTOM (solid shape): 18.49,80.62 18.53,80.6 18.54,80.57 18.54,68.07 18.53,68.04 18.49,68.02 10.87,68.02 5.99,72.9 5.99,77.34 5.97,77.37 5.97,77.52 5.98,77.56 6.02,77.57 7.9,77.57 8.51,76.96 8.51,73.84 11.93,70.42 14.95,70.42 15.54,71.02 15.54,80.11 16.05,80.62
N17241873 on BOTTOM (solid shape): 68.61,34.37 68.61,29.9 68.58,29.87 67.44,29.87 67.41,29.88 67.39,29.89 67.39,29.92 67.39,31.83 65.86,33.35 64.08,33.35 63.65,33.78 63.65,34.33 66.47,34.33 66.48,34.27 66.49,34.22 66.51,34.16 66.53,34.11 66.57,34.07 66.61,34.03 66.65,33.99 66.7,33.96 66.75,33.94 66.81,33.93 66.86,33.92 66.92,33.92 66.98,33.93 67.03,33.95 67.08,33.98 67.13,34.01 67.17,34.05 67.21,34.09 67.24,34.14 67.26,34.19 67.28,34.24 67.28,34.3 67.28,34.36 67.28,34.41 67.26,34.47 67.24,34.52 67.21,34.57 67.17,34.61 67.13,34.65 67.08,34.68 67.03,34.71 66.98,34.72 66.92,34.73 66.86,34.73 66.81,34.73 66.75,34.72 66.7,34.69 66.65,34.67 66.61,34.63 66.57,34.59 66.53,34.54 66.51,34.49 66.49,34.44 66.48,34.38 66.47,34.33 63.65,34.33 63.65,34.68 64.31,35.33 67.64,35.33
N17285521 on BOTTOM (solid shape): 77.37,22.35 77.37,21.51 77.47,21.41 77.47,20.4 76.45,20.4 76.45,21.49 76.71,21.74 76.71,22.45 77.27,22.45
N17473523 on BOTTOM (solid shape): 74.38,46.43 75.21,46.43 75.51,46.13 75.51,44.17 75.08,43.74 75.08,43.31 75.11,43.28 75.11,42.93 75.09,42.89 75.06,42.88 74.63,42.88 74.59,42.89 74.57,42.93 74.57,43.46 74.24,43.79 72.62,43.79 72.19,43.36 72.19,42.34 72.17,42.31 72.14,42.29 71.73,42.29 71.69,42.31 71.68,42.34 71.68,43.94 72.06,44.32 73.03,44.32 73.25,44.55 73.25,46.48 73.28,46.51 74.3,46.51
N17490351 on BOTTOM (solid shape): 74.17,43.18 74.17,40.82 74.14,40.79 73.23,40.79 73.19,40.81 73.18,40.84 73.18,43.26 73.3,43.38 73.96,43.38
N17533679 on BOTTOM (solid shape): 58.29,29.95 58.29,26.7 58.04,26.44 57.89,26.44 57.89,26.29 57.73,26.14 57.73,26.03 57.78,25.98 57.78,25.17 57.77,25.14 57.73,25.12 56.64,25.12 56.59,25.17 56.59,30 56.9,30.3 57.94,30.3

Small or netless copper shapes (teardrops, artwork), in the pictures only: 1 on TOP, 6 on BOTTOM

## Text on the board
BOTTOM: 100-0321321-A1
Ref Des/Silkscreen Bottom: VCCIO_1.8V | PROPRIETARY NOTICE: | THIS DOCUMENT CONTAINS PROPRIETARY INFORMATION | OF INTEL CORP. NEITHER THE DOCUMENT NOR SAID | PROPRIETARY INFORMATION SHALL BE PUBLISHED, | REPRODUCED, COPIED, DISCLOSED OR USED FOR ANY | PURPOSE OTHER THAN CONSIDERATION OF THIS DOCUMENT | WITHOUT THE EXPRESS WRITTEN PERMISSION OF A DULY | AUTHORIZED REPRESENTATIVE OF INTEL CORPORATION | DWG NO. | 130-0321321-A1 | SIZE | SCALE: 1/1 | D | REV | A1 | CAGE CODE | N/A | SHEET 2 OF 2 | P/N | S/N | SECONDARY SIDE SHOWN
Ref Des/Silkscreen Top: C | 2017 INTEL CORP. | Ethernet | LED2 | LED1 | LED0 | GND | VCC_3.3V | VCC_1.8V | VCC_5V | B | D | F | H | K | M | P | E | G | J | L | N | R | 2 | VCC_2.5V | 3 | 4 | 5 | 6 | 7 | 8 | 9 | 10 | 13 | 11 | 12 | 14 | 15 | VCCD_PLL | VCC_1.2V | RESET | CONF | PB0 | PB1 | PB3 | PB2 | BYPASS | DIP0 | DIP1 | DIP2 | POWER | CONFIG | LED3 | Cyclone 10 LP FPGA Evaluation Kit | JTAG | 5V_DC | USB | 2x20 GPIO | THIS DOCUMENT CONTAINS PROPRIETARY INFORMATION | OF INTEL CORP. NEITHER THE DOCUMENT NOR SAID | PROPRIETARY INFORMATION SHALL BE PUBLISHED, | REPRODUCED, COPIED, DISCLOSED OR USED FOR ANY | PURPOSE OTHER THAN CONSIDERATION OF THIS DOCUMENT | WITHOUT THE EXPRESS WRITTEN PERMISSION OF A DULY | AUTHORIZED REPRESENTATIVE OF INTEL CORPORATION | PROPRIETARY NOTICE: | DASH | PROJECTION | XX-XXX-XXXX | NEXT ASSY | APPLICATION | UNLESS OTHERWISE SPECIFIED: | DIMENSIONS ARE IN INCHES IN | ACCORDANCE WITH ANSI Y14.5. | DRILL TOLERANCES ARE PER 10387 | USED ON | SPEC | FNSH | TOLERANCES: | DEC .XXXX  .002 | DEC .X | DEC .XX   .01 | DEC .XXX  .005 | FRACTIONS | ANGLES    1 | + | - | o | CHKR | RELEASE | DWN | DSGN ENGR | CONTRACT NO. | DWG NO. | PSG Board Design Team | 130-0321321-A1 | XXXXXXXX | 14-MAY-2017 | REV | SIZE | TITLE | SCALE: 1/1 | A1 | DESCRIPTION | CAGE CODE | N/A | REVISIONS | PCB ASSEMBLY | DATE | SHEET 1 OF 1 | APPROVED | 19 | 21 | 23 | SAN JOSE, CA 95134 | 101 INNOVATION DRIVE | (c) 2017 INTEL Corporation | NOTES: UNLESS OTHERWISE SPECIFIED | 8.  INSTALL BAR CODE LABEL APPROX WHERE SHOWN, INCLUDING S/N. | 1.  ASSEMBLY HOUSE TO VISUALLY VERIFY BOARD BEING ASSEMBLED HAS | 2.  BOARDS MUST BE BAKED FOR A DURATION OF 8 HOURS AT 250 DEGREES | FARENHEIT IMMEDIATELY PRIOR TO ASSEMBLY. | 3.  ASSEMBLE BOARD PER IPC-A-610(LATEST REVISION) STANDARD. | 4.  ALL MATERIALS USED MUST BE RoHS COMPLIANT. | 5.  HANDLE MOISTURE SENSITIVE DEVICES(MSD) PER MANUFACTURE'S | CALL OUT ON MSD LABEL.  IF MSD LABEL IS MISSING OR NOT LEGIBLE | 6.  REWORK MUST BE APPROVED BY CUSTOMER BEFORE BEING ACCEPTIBLE | USE IPC-R-700(LATEST REVISION) FOR ALL PCA REWORK APPROVED. | 7.  SQUARE PIN PAD DENOTE PIN 1 OF ICs/CONNECTORS, POSITIVE END | FOR CAPACITORS OR CATHODE END FOR DIODES. | 9.  VENDOR TO KEEP QUALITY CONTROL INK STAMPINGS OFF SIGNAL TRACES | AND PADS EVEN IF COVERED BY SOLDERMASK. | INTEL P/N 100-0321321-A1 IN ETCH ON BOTTOM SIDE. | THEN ALL PLASTIC PACKAGED COMPONENTS ARE TO BE CONSIDERED MSD | LEVEL 6 AND USE EIA/JEP 113-A FOR HANDLING. | PRIMARY SIDE SHOWN
DIMENSION: +/-10% | 1OZ | L6 | L3 | L1 | 5.3 | 4 | 5.2/7.8 | 4.2/8.8 | 3.5/11.5 | 50 | 90 | 100 | L5 | L2;L4 | L2 | Via  Technic: | Spell Mode: | Bow and Twist Tolerance:<=0.7% | Inspectionstandard: | Compare With IPC File: | (unit:mil)MIN.track :                       MIN.spacing :                 MIN.hole: | Outline Profile: | Silk Screen Colours: | Dielectric Material: | Soldermask Colours: | Surface Finished: | Finger Chamfer: | 5.5 | / | Hasl Lead Free | Yes | Green | White | Router | Hasl | Spacing | All via (<=0.5mm) must be filled(except open soldermask via) | IPCII | Pressfit holes: The tolerance of                 is+/-0.05mm | Angle | Board Thickness(MM): | IPCIII | 20 | Bridge | Immersion Tin | No | Yellow | Flash Gold | Blue | Open Windows: | 5 | Matte Green | Black | Immersion Gold | Immersion Silver | 30 | GJB362B | V-cut | None | Layers: | Gold Finger | Other | 45 | 10 | By gerber | Stamp Hole | QJ831B | Osp | IT180A | PP | Core | 1.6 | 6 | 3.150(mil) | 38.268(mil) | 3.520(mil) | Note:If etch layer don't have  above impedance track pls ignore | 1.  STACKING (dielectric thickness can be adjusted beween +/-2mil,but don,t less than 3.5mil; | IF inspection is GJB362B or QJ831B then don,t less than 4mil.) | 2.  Control Impedance (track width can be adjusted +/-0.5mil , but don,t less than 4mil.) | ref layer | * | GND05 | VCC04 | TOP | GND02 | ART03 | BOTTOM | PSG Board Design Team | Purchase   Order &  Specification   Sheet | Board Name: | Lead Time: | SSC PN: | PROPRIETARY NOTICE: | THIS DOCUMENT CONTAINS PROPRIETARY INFORMATION | OF INTEL CORP. NEITHER THE DOCUMENT NOR SAID | PROPRIETARY INFORMATION SHALL BE PUBLISHED, | REPRODUCED, COPIED, DISCLOSED OR USED FOR ANY | PURPOSE OTHER THAN CONSIDERATION OF THIS DOCUMENT | WITHOUT THE EXPRESS WRITTEN PERMISSION OF A DULY | AUTHORIZED REPRESENTATIVE OF INTEL CORPORATION | DASH | THIRD ANGLE | PROJECTION | XX-XXX-XXXX | NEXT ASSY | APPLICATION | UNLESS OTHERWISE SPECIFIED: | DIMENSIONS ARE IN INCHES IN | ACCORDANCE WITH ANSI Y14.5. | DRILL TOLERANCES ARE PER 10387 | USED ON | SPEC | FNSH | MATL | EE: | DATE: | MAY-14-2017 | [c]2017 Intel Corporation | 101 INNOVATION DRIVE | SAN JOSE, CA. 95134 | TOLERANCES: | DESIGNER: | SHEET | DEC .XXXX  .002 | OF 1 | DEC .X | DEC .XX   .01 | DEC .XXX  .005 | FRACTIONS | ANGLES    1 | TITLE | FILM TITLE | + | - | DOCUMENT NUMBER | 140-0321321-A1 | o | Cyclone 10 LP FPGA Evaluation Kit | CHKR | RELEASE | DWN | DSGN ENGR | CONTRACT NO. | DWG NO. | XXXXXXXX | 14-MAY-2017 | REV | A1 | SIZE | D | SCALE: 1/1 | CAGE CODE | N/A | DESCRIPTION | REVISIONS | PCB FABRICATION | DATE | SHEET 1 OF 1 | APPROVED | 19 | 8 | 3 | 21 | 23 | (c) 2017 INTEL Corporation | SAN JOSE, CA 95134 | (LATEST REVISION). | NOTES UNLESS OTHERWISE SPECIFIED: | 1. PCB VENDOR MUST NOTIFY RESPONSIBLE INTEL PCB CONTACT OF ANY DISCREPANCIES | FOUND BETWEEN FABRICATION DATA AND FABRICATION DRAWING NOTES. | 2. THIS DRAWING IS VIEWED FROM THE PRIMARY OR TOP SIDE OF THE PCB. | 3  FABRICATION OF THIS PCB SHALL BE IN CONFORMANCE WITH THE FOLLOWING | SPECIFICATIONS: IPC-6011 CLASS 2 (GENERIC). | 4. ALL MATERIALS USED MUST BE RoHS COMPLIANT. | 5. FABRICATION OF THIS PCB TO BE ACCEPTABLE TO IPC-A-600 CLASS 2 | 6. ALL DIMENSIONAL LIMITS APPLY AFTER PLATING OR PROCESSING. | 7. TOLERANCES OF DATUM HOLE TO:  BOARD EDGE LOCATIONS +/- 0.010. | DRILLED HOLE LOCATIONS +/- 0.003. | V-SCORE LOCATIONS +/- 0.010 | 8  BASE MATERIAL: IT180A | 9. FLAME CLASS: UL 94V-0 & MUST MEET REQUIREMENTS OF UL796. | 10. MANUFACTURER MUST BE UL RECOGNIZED TO PRODUCE THIS PRODUCT SUCH THAT | 11  THE FOLLOWING MUST BE MARKED OR ETCHED ON SECONDARY SIDE OF PCB IN AREA | SHOWN: | a)  DATE CODE. | b)  UL RECOGNIZED VENDOR ID, UL TYPE DESIGNATION AND/OR MARKINGS WHICH | REFLECT THE SPECIFIED FLAME CLASS AND MAXIMUM OPERATING TEMPERATURE | RATINGS. | 12. PCB VENDOR TO ENSURE ALL UNCONNECTED (NON-FUNCTIONAL) INTERNAL SIGNAL | LAYER PADS AND VIAS ARE REMOVED. | 13. HOLE/SLOT PLATING = 0.001 MIN. AVERAGE / 0.0008 ABSOLUTE MIN. PLATING. | HOLE/SLOT DIAMETERS ARE SPECIFIED AFTER PLATING (SEE HOLE SCHEDULE). | 14  THESE VIA IN PAD MUST BE VIA FILLED USING NON-CONDUCTIVE | 15. AFTER REVIEWING FABRICATION DATA, PCB VENDOR MUST DISCUSS WHETHER COPPER | THIEVING IS NECESSARY WITH THE RESPONSIBLE INTEL PCB CONTACT.  WHEN | DETERMINED NECESSARY.  A SPACING OF 100 MILS FROM ANY OTHER COPPER FEATURE | ON THE BOARD MUST BE MAINTAINED. | 16. SMEAR REMOVAL SHALL NOT ETCHBACK GREATER THAN 0.001. | 17. FINISHED CONDUCTOR WIDTH NOT TO BE REDUCED MORE THAN 20% OF MINIMUM WIDTH | FROM ARTWORK SUPPLIED. FINISHED CONDUCTOR SPACING NOT TO BE REDUCED MORE | THAN 20% OF MINIMUM SPACING FROM ARTWORK SUPPLIED. | 18. TEAR DROPPING OF TRACE TO PAD JUNCTION IS PERMITTED PROVIDED MINIMUM | METAL-TO-METAL ARTWORK SPACINGS ARE NOT COMPROMISED. | 19  SOLDER MASK IS LIQUID PHOTO IMAGEABLE AND IN ACCORDANCE WITH IPC-SM-840C | CLASS T.  FINISH MUST BE GREEN AND GLOSSY. REGISTRATION TO BE WITHIN | +/- 0.003 OF ITS RESPECTIVE OUTER CIRCUIT LAYERS. VENDOR MAY ADJUST | SOLDERMASK WHEREVER SOLDERMASK PADS ARE THE SAME SIZE (1:1) TO PROVIDE UP | TO .003 MAXIMUM CLEARANCE FROM MASK TO PAD PROVIDED NO ADJACENT COPPER IS | EXPOSED AND NO CONFLICT IS PRODUCED WITH ANY STATED "VIA TENTING/PLUGGING" | REQUIREMENTS. | 20  PCB VENDOR TO ENSURE VIAS ARE SOLDERMASK ENCROACHED ON BOTTOM SIDE OF | PCB, EXCEPT IN AREAS SHOWN DUE TO BOTTOM MOUNT BGA PACKAGES. | 21  PCB FINISH BOTH SIDES TO BE ELECTROLESS NICKEL (Ni) FOLLOWED BY IMMERSION | GOLD (AU) (ENIG) ACCEPTABLE TO IPC-4552. | 22. REMOVE ALL SHARP EDGES AND BURRS 0.003" MAXIMUM. | 23  SILKSCREEN USING WHITE NONCONDUCTIVE INK. NO INK TO APPEAR ON EXPOSED | COPPER SUCH AS PLATED THROUGH HOLE PADS AND SURFACE MOUNT LANDS. INK | ON SOLDER MASK COVERED PADS IS PERMISSIBLE. CLIPPING OF SILKSCREEN | 0.008 MAX. FROM PADS IS PERMITTED. | 24. BOW & TWIST SHALL BE DETERMINED BY PHYSICAL MEASUREMENT AND PERCENTAGE | CALCULATION IN ACCORDANCE WITH IPC-TM-650, METHOD 2.4.22. BOW AND TWIST | MAY NOT EXCEED 0.7% | 25. 100% CONTINUITY AND ISOLATION ELECTRICAL TESTING PER CURRENT IPC TEST | METHODS REQUIRED FOR EVERY PCB. FINAL PCB TEST DATA MUST BE CROSS- | REFERENCED TO IPC-D-356 FILE, NEUTRAL FILE OR NETLIST PROVIDED. | 26. PCB VENDOR TO PROVIDE ONE TEST COUPON AND ONE CROSS SECTION PER LOT WITH | SHIPMENT. | 27. PCB VENDOR TO PROVIDE 2 SOLDER SAMPLES WITH FIRST SHIPMENT. | 28  VENDOR TO KEEP QUALITY CONTROL INK STAMPINGS ON BOTTOM OF PCB IN AREA | SPECIFIED.  STAMPINGS CANNOT BE ON TRACES OR PADS EVEN IF COVERED BY MASK. | 29. DETAILS NOT SPECIFIED ARE AT MANUFACTURER'S OPTION, HOWEVER | FINAL APPROVAL MUST BE OBTAINED. | IT MEETS 130 DEGREES CELSIUS MAXIMUM OPERATING TEMPERATURE (MOT). | EPOXY VIA FILL, PLANARIZED AND PLATED OVER.
DEVICE_TYPE_TOP: V-CUT
